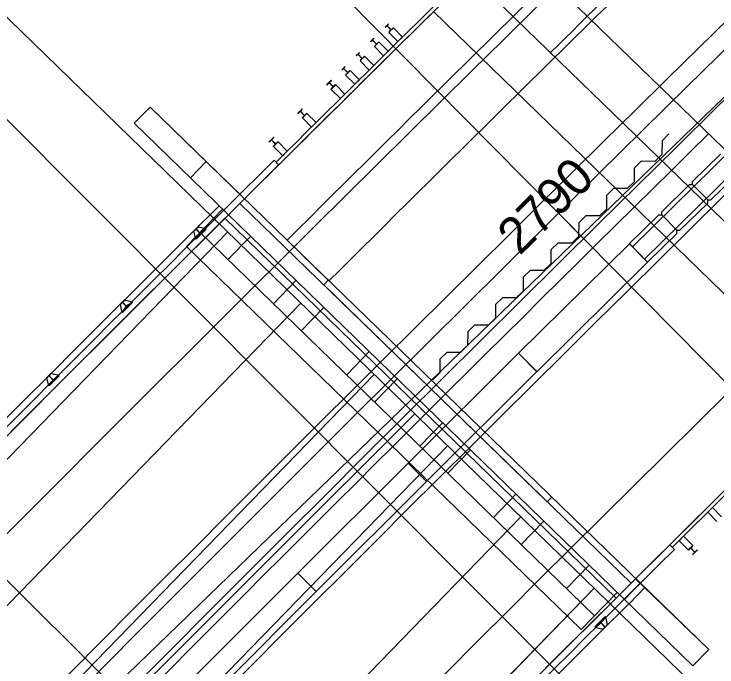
# Model space of a CAD drawing. Extents: x 2376379 to 2383101, y 559608 to 561720.
# Drawn here: x 2377103.1 to 2377157.2, y 561323.6 to 561373.9 of the extents above; entities that cross this region are included whole.
import ezdxf

# ---------------------------------------------------------------- set-up
doc = ezdxf.new("R2010")
doc.units = 0
for name, color, linetype in [('BR_X_SV_Bottom_of_Beam', 7, 'Continuous'), ('BR_X_SV_Deck_Top', 7, 'Continuous'), ('DR_X_Storm_Sewer', 7, 'Continuous'), ('DT_X_Contour_Minor', 7, 'Continuous'), ('DT_X_Terrain_Ground_Line', 7, 'Continuous'), ('HY_X_Water_Edge', 7, 'Continuous'), ('PM_X_CL_Dashed', 7, 'Continuous'), ('PM_X_CL_Pass_Proh_Lt', 7, 'Continuous'), ('PM_X_Edge_Line', 7, 'Continuous'), ('PM_X_Surveyed_Line', 7, 'Continuous'), ('PV_X_COP', 7, 'Continuous'), ('PV_X_EOP', 7, 'Continuous'), ('PV_X_Shoulder', 7, 'Continuous'), ('RD_X_Cells', 7, 'Continuous'), ('SC_Scratch1', 7, 'Continuous'), ('SV_X_Break_Lines', 7, 'Continuous'), ('SV_X_Control_Cells_Found', 7, 'Continuous'), ('SV_X_Text', 7, 'Continuous'), ('UT_X_Gas_Cells', 7, 'Continuous')]:
    doc.layers.add(name, color=color, linetype=linetype)

msp = doc.modelspace()

# ---------------------------------------------------------------- linework, layer by layer
at = {"layer": 'BR_X_SV_Bottom_of_Beam'}
for p, q in [((2377150.716, 561355.991), (2377168.891, 561373.861)), ((2377169.826, 561372.91), (2377151.651, 561355.041)), ((2377157.494, 561363.123), (2377155.355, 561361.02)), ((2377158.896, 561361.697), (2377156.757, 561359.594)), ((2377155.353, 561360.784), (2377155.355, 561361.02)), ((2377155.117, 561360.786), (2377152.978, 561358.683)), ((2377155.117, 561360.786), (2377155.353, 561360.784)), ((2377155.353, 561360.784), (2377156.521, 561359.596)), ((2377156.519, 561359.36), (2377154.38, 561357.257)), ((2377156.519, 561359.36), (2377156.521, 561359.596)), ((2377156.521, 561359.596), (2377156.757, 561359.594)), ((2377152.976, 561358.447), (2377152.978, 561358.683)), ((2377152.74, 561358.449), (2377150.482, 561356.229)), ((2377152.74, 561358.449), (2377152.976, 561358.447)), ((2377152.976, 561358.447), (2377154.145, 561357.259)), ((2377154.143, 561357.023), (2377154.145, 561357.259)), ((2377154.145, 561357.259), (2377154.38, 561357.257)), ((2377154.143, 561357.023), (2377151.884, 561354.803)), ((2377150.48, 561356.227), (2377141.951, 561347.786)), ((2377150.48, 561356.227), (2377141.951, 561347.786)), ((2377150.48, 561356.227), (2377151.887, 561354.805)), ((2377150.48, 561356.227), (2377151.887, 561354.805)), ((2377150.482, 561356.229), (2377151.884, 561354.803)), ((2377151.887, 561354.805), (2377143.358, 561346.364)), ((2377151.887, 561354.805), (2377143.358, 561346.364)), ((2377141.949, 561347.784), (2377133.438, 561339.325)), ((2377141.949, 561347.784), (2377143.359, 561346.366)), ((2377141.951, 561347.786), (2377143.358, 561346.364)), ((2377141.951, 561347.786), (2377143.358, 561346.364)), ((2377143.359, 561346.366), (2377134.848, 561337.907)), ((2377133.436, 561339.324), (2377124.942, 561330.847)), ((2377133.436, 561339.324), (2377134.849, 561337.908)), ((2377133.438, 561339.325), (2377134.848, 561337.907)), ((2377134.849, 561337.908), (2377126.355, 561329.431)), ((2377124.941, 561330.845), (2377116.465, 561322.351)), ((2377124.941, 561330.845), (2377126.357, 561329.433)), ((2377124.942, 561330.847), (2377126.355, 561329.431)), ((2377126.357, 561329.433), (2377117.881, 561320.938))]:
    msp.add_line(p, q, dxfattribs=at)
for radius in [5724.68, 5713.68]:
    msp.add_arc((2381174.86, 557281.309), radius, 134.056462, 138.414594, dxfattribs=at)
at = {"layer": 'BR_X_SV_Deck_Top'}
msp.add_line((2377124.116, 561356.5), (2377127.344, 561353.364), dxfattribs=at)
for radius, end in [(5745.93, 134.8276325), (5741.43, 134.826849)]:
    msp.add_arc((2381174.86, 557281.309), radius, 134.0564619, end, dxfattribs=at)
at = {"layer": 'DR_X_Storm_Sewer'}
for p, q in [((2377138.249, 561376.921), (2377168.38, 561347.648)), ((2377120.481, 561359.334), (2377150.61, 561330.063))]:
    msp.add_line(p, q, dxfattribs=at)
for radius, start, end in [(5750.58, 134.5843481, 134.8334349), (5708.58, 134.575202, 134.826122)]:
    msp.add_arc((2381174.917, 557281.256), radius, start, end, dxfattribs=at)
at = {"layer": 'DT_X_Contour_Minor'}
msp.add_lwpolyline([(2377106.696, 561285.936), (2377105.962, 561286.648), (2377147.772, 561329.683), (2377149.014, 561328.476)], dxfattribs=at)
at = {"layer": 'DT_X_Terrain_Ground_Line'}
for p, q in [((2377141.099, 561379.729), (2377171.231, 561350.455)), ((2377135.4, 561374.112), (2377165.531, 561344.839))]:
    msp.add_line(p, q, dxfattribs=at)
at = {"layer": 'HY_X_Water_Edge'}
msp.add_line((2377054.072, 561420.716), (2377215.816, 561263.576), dxfattribs=at)
at = {"layer": 'PM_X_CL_Dashed'}
for p, q in [((2377123.467, 561362.299), (2377123.114, 561362.654)), ((2377156.523, 561335.535), (2377156.879, 561335.887)), ((2377157.227, 561334.825), (2377156.523, 561335.535)), ((2377157.582, 561335.177), (2377156.879, 561335.887)), ((2377154.305, 561333.335), (2377154.66, 561333.687)), ((2377155.009, 561332.625), (2377154.305, 561333.335)), ((2377155.364, 561332.978), (2377154.66, 561333.687)), ((2377153.949, 561332.674), (2377153.597, 561333.029)), ((2377155.364, 561332.977), (2377155.009, 561332.626)), ((2377155.195, 561332.779), (2377155.025, 561332.61)), ((2377155.195, 561332.779), (2377155.516, 561332.456)), ((2377155.379, 561332.962), (2377155.209, 561332.793)), ((2377155.209, 561332.793), (2377155.53, 561332.469)), ((2377155.364, 561332.977), (2377155.379, 561332.962)), ((2377155.009, 561332.626), (2377155.025, 561332.61)), ((2377155.516, 561332.456), (2377155.346, 561332.287)), ((2377155.346, 561332.287), (2377155.361, 561332.271)), ((2377155.715, 561332.623), (2377155.361, 561332.271)), ((2377155.7, 561332.638), (2377155.53, 561332.469)), ((2377155.7, 561332.638), (2377155.715, 561332.623)), ((2377148.451, 561327.21), (2377148.658, 561327.416)), ((2377148.658, 561327.416), (2377148.6, 561327.475)), ((2377148.665, 561327.364), (2377148.636, 561327.394)), ((2377148.665, 561327.364), (2377148.771, 561326.855)), ((2377147.89, 561326.652), (2377148.097, 561326.858)), ((2377148.451, 561327.21), (2377148.097, 561326.858)), ((2377148.097, 561326.858), (2377148.113, 561326.843)), ((2377148.283, 561327.012), (2377148.113, 561326.843)), ((2377148.283, 561327.012), (2377148.604, 561326.689)), ((2377148.467, 561327.195), (2377148.296, 561327.026)), ((2377148.296, 561327.026), (2377148.618, 561326.702)), ((2377148.803, 561326.856), (2377148.45, 561326.504)), ((2377148.451, 561327.21), (2377148.467, 561327.195)), ((2377148.788, 561326.872), (2377148.618, 561326.702)), ((2377148.788, 561326.872), (2377148.803, 561326.856)), ((2377147.89, 561326.652), (2377147.832, 561326.711)), ((2377147.943, 561326.645), (2377147.913, 561326.675)), ((2377147.943, 561326.645), (2377148.451, 561326.536)), ((2377148.604, 561326.689), (2377148.434, 561326.52)), ((2377148.434, 561326.52), (2377148.45, 561326.504))]:
    msp.add_line(p, q, dxfattribs=at)
msp.add_lwpolyline([(2377147.832, 561326.711), (2377147.832, 561326.711), (2377148.6, 561327.475)], dxfattribs=at)
for centre, radius, start, end in [((2381174.86, 557281.309), 5708.502, 134.056462, 138.734789), ((2381174.917, 557281.256), 5708.299, 134.056498, 134.783877), ((2381174.86, 557281.309), 5708.002, 134.783851, 136.871541)]:
    msp.add_arc(centre, radius, start, end, dxfattribs=at)
at = {"layer": 'PM_X_CL_Pass_Proh_Lt'}
for p, q in [((2377131.67, 561372.92), (2377131.904, 561373.15)), ((2377131.683, 561372.907), (2377131.67, 561372.92)), ((2377131.683, 561372.907), (2377131.795, 561373.017)), ((2377131.795, 561373.017), (2377132.115, 561372.693)), ((2377131.805, 561373.027), (2377131.916, 561373.138)), ((2377131.805, 561373.027), (2377132.125, 561372.703)), ((2377131.916, 561373.138), (2377131.904, 561373.15)), ((2377132.016, 561372.57), (2377132.249, 561372.801)), ((2377132.125, 561372.703), (2377132.237, 561372.813)), ((2377132.249, 561372.801), (2377132.237, 561372.813)), ((2377132.311, 561372.861), (2377132.249, 561372.801)), ((2377132.311, 561372.861), (2377133.013, 561372.15)), ((2377132.016, 561372.57), (2377131.955, 561372.51)), ((2377131.955, 561372.51), (2377132.658, 561371.798)), ((2377132.003, 561372.583), (2377132.115, 561372.693)), ((2377132.003, 561372.583), (2377132.016, 561372.57)), ((2377130.56, 561371.822), (2377130.793, 561372.053)), ((2377130.572, 561371.809), (2377130.56, 561371.822)), ((2377130.572, 561371.809), (2377130.684, 561371.919)), ((2377130.684, 561371.919), (2377131.004, 561371.595)), ((2377130.694, 561371.929), (2377130.806, 561372.04)), ((2377130.694, 561371.929), (2377131.014, 561371.605)), ((2377130.806, 561372.04), (2377130.793, 561372.053)), ((2377130.905, 561371.472), (2377131.139, 561371.703)), ((2377131.014, 561371.605), (2377131.126, 561371.716)), ((2377131.139, 561371.703), (2377131.126, 561371.716)), ((2377131.2, 561371.763), (2377131.139, 561371.703)), ((2377131.2, 561371.763), (2377131.903, 561371.052)), ((2377133.013, 561372.15), (2377132.658, 561371.798)), ((2377130.905, 561371.472), (2377130.844, 561371.412)), ((2377130.844, 561371.412), (2377131.547, 561370.701)), ((2377130.893, 561371.485), (2377131.004, 561371.595)), ((2377130.893, 561371.485), (2377130.905, 561371.472)), ((2377129.449, 561370.724), (2377129.683, 561370.955)), ((2377129.462, 561370.711), (2377129.449, 561370.724)), ((2377129.462, 561370.711), (2377129.573, 561370.821)), ((2377129.573, 561370.821), (2377129.894, 561370.497)), ((2377129.584, 561370.831), (2377129.695, 561370.942)), ((2377129.584, 561370.831), (2377129.904, 561370.507)), ((2377129.695, 561370.942), (2377129.683, 561370.955)), ((2377129.795, 561370.374), (2377130.028, 561370.605)), ((2377129.904, 561370.507), (2377130.016, 561370.618)), ((2377130.028, 561370.605), (2377130.016, 561370.618)), ((2377130.089, 561370.665), (2377130.028, 561370.605)), ((2377130.089, 561370.665), (2377130.793, 561369.954)), ((2377131.903, 561371.052), (2377131.547, 561370.701)), ((2377129.795, 561370.374), (2377129.734, 561370.314)), ((2377129.734, 561370.314), (2377130.437, 561369.603)), ((2377129.782, 561370.387), (2377129.894, 561370.497)), ((2377129.782, 561370.387), (2377129.795, 561370.374)), ((2377128.339, 561369.625), (2377128.572, 561369.856)), ((2377128.352, 561369.612), (2377128.339, 561369.625)), ((2377128.352, 561369.612), (2377128.463, 561369.723)), ((2377128.463, 561369.723), (2377128.784, 561369.399)), ((2377128.473, 561369.733), (2377128.585, 561369.843)), ((2377128.473, 561369.733), (2377128.794, 561369.409)), ((2377128.585, 561369.843), (2377128.572, 561369.856)), ((2377128.685, 561369.276), (2377128.918, 561369.507)), ((2377128.794, 561369.409), (2377128.906, 561369.519)), ((2377128.918, 561369.507), (2377128.906, 561369.519)), ((2377128.979, 561369.567), (2377128.918, 561369.507)), ((2377128.979, 561369.567), (2377129.683, 561368.856)), ((2377130.793, 561369.954), (2377130.437, 561369.603)), ((2377128.685, 561369.276), (2377128.624, 561369.215)), ((2377128.624, 561369.215), (2377129.327, 561368.505)), ((2377128.672, 561369.288), (2377128.784, 561369.399)), ((2377128.672, 561369.288), (2377128.685, 561369.276)), ((2377127.163, 561368.472), (2377127.518, 561368.823)), ((2377127.179, 561368.456), (2377127.163, 561368.472)), ((2377127.179, 561368.456), (2377127.349, 561368.625)), ((2377127.67, 561368.301), (2377127.349, 561368.625)), ((2377127.363, 561368.639), (2377127.533, 561368.807)), ((2377127.683, 561368.315), (2377127.363, 561368.639)), ((2377127.515, 561368.117), (2377127.869, 561368.468)), ((2377127.533, 561368.807), (2377127.518, 561368.823)), ((2377127.683, 561368.315), (2377127.854, 561368.484)), ((2377127.869, 561368.468), (2377127.854, 561368.484)), ((2377127.87, 561368.468), (2377128.573, 561367.758)), ((2377129.683, 561368.856), (2377129.327, 561368.505)), ((2377127.499, 561368.132), (2377127.67, 561368.301)), ((2377127.515, 561368.117), (2377127.499, 561368.132)), ((2377127.514, 561368.117), (2377128.218, 561367.406)), ((2377128.573, 561367.758), (2377128.218, 561367.406)), ((2377124.943, 561366.271), (2377125.297, 561366.623)), ((2377124.958, 561366.256), (2377124.943, 561366.271)), ((2377124.958, 561366.256), (2377125.128, 561366.425)), ((2377125.449, 561366.101), (2377125.128, 561366.425)), ((2377125.142, 561366.438), (2377125.312, 561366.607)), ((2377125.463, 561366.115), (2377125.142, 561366.438)), ((2377125.294, 561365.917), (2377125.649, 561366.268)), ((2377125.312, 561366.607), (2377125.297, 561366.623)), ((2377125.463, 561366.115), (2377125.633, 561366.284)), ((2377125.649, 561366.268), (2377125.633, 561366.284)), ((2377125.649, 561366.268), (2377126.353, 561365.558)), ((2377125.279, 561365.932), (2377125.449, 561366.101)), ((2377125.294, 561365.917), (2377125.279, 561365.932)), ((2377125.294, 561365.916), (2377125.998, 561365.206)), ((2377126.353, 561365.558), (2377125.998, 561365.206)), ((2377122.723, 561364.07), (2377123.077, 561364.421)), ((2377122.738, 561364.054), (2377122.909, 561364.223)), ((2377123.23, 561363.9), (2377122.909, 561364.223)), ((2377122.922, 561364.237), (2377123.093, 561364.406)), ((2377123.243, 561363.913), (2377122.922, 561364.237)), ((2377123.093, 561364.406), (2377123.077, 561364.421)), ((2377123.243, 561363.913), (2377123.414, 561364.082)), ((2377123.429, 561364.067), (2377123.414, 561364.082)), ((2377122.738, 561364.054), (2377122.723, 561364.07)), ((2377123.06, 561363.731), (2377123.23, 561363.9)), ((2377123.075, 561363.715), (2377123.06, 561363.731)), ((2377123.074, 561363.715), (2377123.779, 561363.005)), ((2377123.075, 561363.715), (2377123.429, 561364.067)), ((2377123.429, 561364.067), (2377124.134, 561363.357)), ((2377124.134, 561363.357), (2377123.779, 561363.005)), ((2377116.911, 561357.191), (2377117.265, 561357.543)), ((2377116.927, 561357.176), (2377116.911, 561357.191)), ((2377116.927, 561357.176), (2377117.097, 561357.345)), ((2377117.05, 561356.684), (2377116.943, 561357.192)), ((2377117.418, 561357.022), (2377117.097, 561357.345)), ((2377117.11, 561357.359), (2377117.28, 561357.528)), ((2377117.432, 561357.036), (2377117.11, 561357.359)), ((2377117.772, 561357.403), (2377117.264, 561357.511)), ((2377117.264, 561356.837), (2377117.617, 561357.19)), ((2377117.28, 561357.528), (2377117.265, 561357.543)), ((2377117.432, 561357.036), (2377117.602, 561357.205)), ((2377117.617, 561357.19), (2377117.602, 561357.205)), ((2377117.824, 561357.396), (2377117.617, 561357.19)), ((2377117.772, 561357.403), (2377117.802, 561357.373)), ((2377117.824, 561357.396), (2377117.883, 561357.337)), ((2377117.05, 561356.684), (2377117.079, 561356.654)), ((2377117.264, 561356.837), (2377117.057, 561356.631)), ((2377117.057, 561356.631), (2377117.115, 561356.572)), ((2377117.248, 561356.853), (2377117.418, 561357.022)), ((2377117.264, 561356.837), (2377117.248, 561356.853)), ((2377111.245, 561351.542), (2377111.598, 561351.895)), ((2377111.26, 561351.527), (2377111.43, 561351.696)), ((2377111.752, 561351.374), (2377111.43, 561351.696)), ((2377111.444, 561351.71), (2377111.614, 561351.879)), ((2377111.766, 561351.387), (2377111.444, 561351.71)), ((2377112.106, 561351.754), (2377111.597, 561351.863)), ((2377111.614, 561351.879), (2377111.598, 561351.895)), ((2377112.158, 561351.748), (2377111.951, 561351.541)), ((2377112.106, 561351.754), (2377112.135, 561351.725)), ((2377112.158, 561351.748), (2377112.217, 561351.689)), ((2377111.26, 561351.527), (2377111.245, 561351.542)), ((2377111.384, 561351.034), (2377111.277, 561351.543)), ((2377111.598, 561351.189), (2377111.391, 561350.982)), ((2377111.582, 561351.204), (2377111.752, 561351.374)), ((2377111.598, 561351.189), (2377111.582, 561351.204)), ((2377111.598, 561351.189), (2377111.951, 561351.541)), ((2377111.766, 561351.387), (2377111.936, 561351.557)), ((2377111.951, 561351.541), (2377111.936, 561351.557)), ((2377111.384, 561351.034), (2377111.414, 561351.005)), ((2377111.391, 561350.982), (2377111.45, 561350.923)), ((2377105.587, 561345.885), (2377105.939, 561346.238)), ((2377105.785, 561346.053), (2377105.955, 561346.223)), ((2377105.955, 561346.223), (2377105.939, 561346.238)), ((2377105.602, 561345.869), (2377105.587, 561345.885)), ((2377105.602, 561345.869), (2377105.772, 561346.039)), ((2377105.727, 561345.377), (2377105.619, 561345.886)), ((2377106.094, 561345.717), (2377105.772, 561346.039)), ((2377106.108, 561345.731), (2377105.785, 561346.053)), ((2377105.924, 561345.547), (2377106.094, 561345.717)), ((2377106.447, 561346.099), (2377105.938, 561346.206)), ((2377105.94, 561345.532), (2377106.293, 561345.885)), ((2377106.108, 561345.731), (2377106.277, 561345.9)), ((2377106.293, 561345.885), (2377106.277, 561345.9)), ((2377106.499, 561346.092), (2377106.293, 561345.885)), ((2377106.447, 561346.099), (2377106.476, 561346.069)), ((2377106.499, 561346.092), (2377106.558, 561346.033)), ((2377105.727, 561345.377), (2377105.756, 561345.348)), ((2377105.94, 561345.532), (2377105.733, 561345.325)), ((2377105.733, 561345.325), (2377105.792, 561345.266)), ((2377105.94, 561345.532), (2377105.924, 561345.547))]:
    msp.add_line(p, q, dxfattribs=at)
for points in [[(2377117.883, 561357.337), (2377117.883, 561357.337), (2377117.115, 561356.572)], [(2377112.217, 561351.689), (2377112.217, 561351.689), (2377111.45, 561350.923)], [(2377106.558, 561346.033), (2377106.558, 561346.033), (2377105.792, 561345.266)]]:
    msp.add_lwpolyline(points, dxfattribs=at)
for centre, radius, start, end in [((2381174.86, 557281.309), 5750.502, 134.4393655, 138.0925584), ((2381174.917, 557281.256), 5750.861, 134.4393973, 134.7915077), ((2381174.917, 557281.256), 5751.08, 134.7915077, 136.8639244)]:
    msp.add_arc(centre, radius, start, end, dxfattribs=at)
at = {"layer": 'PM_X_Edge_Line'}
msp.add_line((2377149.458, 561328.917), (2377119.329, 561358.188), dxfattribs=at)
for centre, radius, start, end in [((2381174.86, 557281.309), 5728.92, 134.539622, 137.114945), ((2381174.917, 557281.256), 5750.58, 134.8496279, 136.8055852), ((2381174.917, 557281.256), 5708.58, 134.842434, 136.812784)]:
    msp.add_arc(centre, radius, start, end, dxfattribs=at)
at = {"layer": 'PM_X_Surveyed_Line'}
for p, q in [((2377231.314, 561271.266), (2377062.604, 561441.962)), ((2377044.49, 561423.98), (2377213.943, 561254.023)), ((2377196.648, 561236.703), (2377026.455, 561405.92))]:
    msp.add_line(p, q, dxfattribs=at)
at = {"layer": 'PV_X_COP'}
for p, q in [((2377154.934, 561368.339), (2377163.498, 561376.745)), ((2377146.387, 561359.915), (2377154.934, 561368.339)), ((2377137.858, 561351.472), (2377146.386, 561359.914)), ((2377129.345, 561343.012), (2377137.856, 561351.471)), ((2377120.851, 561334.534), (2377129.344, 561343.011)), ((2377112.374, 561326.037), (2377120.85, 561334.532)), ((2377103.915, 561317.524), (2377112.373, 561326.036))]:
    msp.add_line(p, q, dxfattribs=at)
for radius in [5745.18, 5734.18]:
    msp.add_arc((2381174.86, 557281.309), radius, 134.0564619, 138.4145938, dxfattribs=at)
at = {"layer": 'PV_X_EOP'}
msp.add_line((2377146.959, 561356.614), (2377145.553, 561358.037), dxfattribs=at)
at = {"layer": 'PV_X_Shoulder'}
msp.add_arc((2381174.917, 557281.256), 5729.58, 134.8522952, 136.8022952, dxfattribs=at)
at = {"layer": 'RD_X_Cells'}
msp.add_line((2376995.664, 561210.671), (2377447.664, 561648.024), dxfattribs=at)
msp.add_arc((2381174.86, 557281.309), 5729.93, 134.0564619, 139.4731285, dxfattribs=at)
msp.add_arc((2381174.86, 557281.309), 5729.93, 134.0564619, 139.4731285, dxfattribs=at)
at = {"layer": 'SC_Scratch1'}
for p, q in [((2377112.338, 561365.503), (2377113.557, 561366.758)), ((2377113.557, 561366.758), (2377120.836, 561359.686)), ((2377155.372, 561323.693), (2377112.338, 561365.503)), ((2377150.965, 561330.415), (2377156.592, 561324.948)), ((2377156.592, 561324.948), (2377155.372, 561323.693))]:
    msp.add_line(p, q, dxfattribs=at)
at = {"layer": 'SV_X_Break_Lines'}
for p, q in [((2377153.531, 561364.683), (2377152.997, 561364.157)), ((2377152.997, 561364.157), (2377152.988, 561363.097)), ((2377152.988, 561363.097), (2377152.453, 561362.571)), ((2377151.393, 561362.579), (2377150.858, 561362.053)), ((2377152.453, 561362.571), (2377151.393, 561362.579)), ((2377150.858, 561362.053), (2377150.85, 561360.993)), ((2377150.85, 561360.993), (2377150.315, 561360.467)), ((2377149.254, 561360.475), (2377148.72, 561359.949)), ((2377150.315, 561360.467), (2377149.254, 561360.475)), ((2377148.72, 561359.949), (2377148.711, 561358.889)), ((2377148.711, 561358.889), (2377148.176, 561358.363)), ((2377147.116, 561358.371), (2377146.581, 561357.845)), ((2377148.176, 561358.363), (2377147.116, 561358.371)), ((2377146.581, 561357.845), (2377146.573, 561356.785)), ((2377146.573, 561356.785), (2377146.038, 561356.259)), ((2377144.977, 561356.267), (2377144.443, 561355.741)), ((2377146.038, 561356.259), (2377144.977, 561356.267)), ((2377144.443, 561355.741), (2377144.434, 561354.681)), ((2377144.434, 561354.681), (2377143.899, 561354.155)), ((2377142.839, 561354.163), (2377142.304, 561353.637)), ((2377143.899, 561354.155), (2377142.839, 561354.163)), ((2377142.304, 561353.637), (2377142.296, 561352.577)), ((2377142.296, 561352.577), (2377141.761, 561352.051)), ((2377140.7, 561352.059), (2377140.166, 561351.533)), ((2377141.761, 561352.051), (2377140.7, 561352.059)), ((2377140.166, 561351.533), (2377140.157, 561350.473)), ((2377140.157, 561350.473), (2377139.622, 561349.947)), ((2377138.562, 561349.955), (2377138.027, 561349.429)), ((2377139.622, 561349.947), (2377138.562, 561349.955)), ((2377138.027, 561349.429), (2377138.019, 561348.369)), ((2377136.423, 561347.851), (2377135.889, 561347.325)), ((2377137.484, 561347.843), (2377136.423, 561347.851)), ((2377138.019, 561348.369), (2377137.484, 561347.843)), ((2377135.889, 561347.325), (2377135.88, 561346.265)), ((2377135.88, 561346.265), (2377135.345, 561345.739))]:
    msp.add_line(p, q, dxfattribs=at)
at = {"layer": 'SV_X_Control_Cells_Found'}
for p, q in [((2377113.557, 561366.758), (2377112.338, 561365.503)), ((2377113.557, 561366.758), (2377156.592, 561324.948)), ((2377112.338, 561365.503), (2377155.372, 561323.693)), ((2377117.891, 561362.548), (2377116.671, 561361.293)), ((2377119.152, 561358.883), (2377116.364, 561356.014)), ((2377117.41, 561357.09), (2377147.803, 561327.562)), ((2377119.561, 561354.999), (2377121.303, 561356.792)), ((2377116.364, 561356.014), (2377146.757, 561326.486)), ((2377123.058, 561351.602), (2377124.8, 561353.395)), ((2377127.289, 561353.417), (2377126.941, 561353.058)), ((2377126.941, 561353.058), (2377144.155, 561336.334)), ((2377125.21, 561349.512), (2377126.952, 561351.305)), ((2377128.706, 561346.115), (2377130.448, 561347.908)), ((2377130.858, 561344.024), (2377132.6, 561345.817)), ((2377134.354, 561340.627), (2377136.096, 561342.42)), ((2377136.506, 561338.537), (2377138.248, 561340.33)), ((2377140.003, 561335.14), (2377141.745, 561336.933)), ((2377144.503, 561336.693), (2377144.155, 561336.334)), ((2377142.154, 561333.049), (2377143.896, 561334.842)), ((2377145.651, 561329.652), (2377147.393, 561331.445)), ((2377151.317, 561330.073), (2377150.098, 561328.818)), ((2377151.676, 561329.725), (2377150.456, 561328.469)), ((2377146.757, 561326.486), (2377149.545, 561329.355)), ((2377156.592, 561324.948), (2377155.372, 561323.693))]:
    msp.add_line(p, q, dxfattribs=at)
for radius, start, end in [(5751.58, 134.8460617, 136.8085286), (5707.58, 134.838497, 136.816094)]:
    msp.add_arc((2381174.917, 557281.256), radius, start, end, dxfattribs=at)
at = {"layer": 'SV_X_Text'}
msp.add_arc((2381174.86, 557281.309), 5741.93, 134.3298716, 134.5824639, dxfattribs=at)
at = {"layer": 'UT_X_Gas_Cells'}
for p, q in [((2377119.531, 561357.12), (2376983.657, 561217.265)), ((2377125.179, 561351.633), (2376989.305, 561211.777)), ((2377130.827, 561346.145), (2376994.953, 561206.29)), ((2377136.475, 561340.658), (2377000.601, 561200.802)), ((2377142.124, 561335.17), (2377006.25, 561195.315)), ((2377147.772, 561329.683), (2377011.898, 561189.827))]:
    msp.add_line(p, q, dxfattribs=at)

# ---------------------------------------------------------------- texts
at = {"layer": 'PV_X_EOP'}
msp.add_text('2790', height=2.8, rotation=44.6648, dxfattribs=at).set_placement((2377142.027, 561355.254))

doc.saveas('drawing.dxf')
